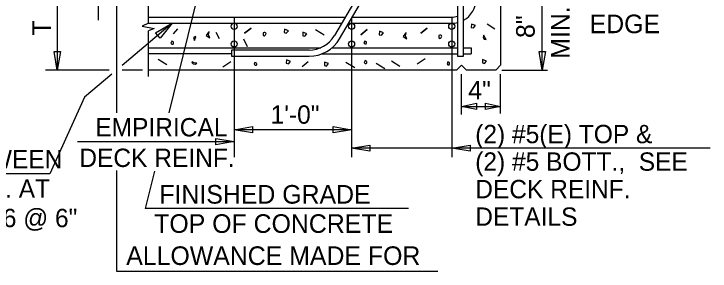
# Model space of a CAD drawing. Extents: x 0 to 34, y 0 to 23.5.
# Drawn here: x 15.91 to 21.84, y 3.54 to 5.73 of the extents above; entities that cross this region are included whole.
import ezdxf

# ---------------------------------------------------------------- set-up
doc = ezdxf.new("R2010")
doc.units = 0
for name, color, linetype in [('BRDG_ANNO_General-Notes', 7, 'Continuous'), ('BRDG_BASE_Dtlctrln', 7, 'Continuous'), ('BRDG_BASE_Obj-Line', 7, 'Continuous'), ('BRDG_BASE_Pattern', 7, 'Continuous'), ('BRDG_BASE_Rebar', 7, 'Continuous'), ('Default', 7, 'Continuous')]:
    doc.layers.add(name, color=color, linetype=linetype)

# ---------------------------------------------------------------- blocks, each defined once
blk = doc.blocks.new('TERM')
at = {"layer": 'Default'}
for p, q in [((-1.6, -0.3), (-1.6, 0.3)), ((-1.6, 0.3), (0, 0)), ((0, 0), (-1.6, -0.3))]:
    blk.add_line(p, q, dxfattribs=at)

msp = doc.modelspace()

# ---------------------------------------------------------------- linework, layer by layer
at = {"layer": 'BRDG_ANNO_General-Notes'}
for p, q in [((16.2812, 5.9219), (16.2812, 5.2552)), ((16.6299, 5.9219), (16.6299, 5.6807)), ((16.7855, 5.9219), (16.7855, 4.8916)), ((17.4854, 5.9219), (17.231, 4.8919)), ((20.4129, 5.2552), (20.4129, 5.9219)), ((17.2603, 5.6546), (16.8331, 5.2948)), ((17.1185, 5.5745), (17.2603, 5.6546)), ((17.2603, 5.6546), (17.1572, 5.5286)), ((17.1572, 5.5286), (17.1185, 5.5745)), ((16.2546, 5.4152), (16.3079, 5.4152)), ((16.2812, 5.2552), (16.2546, 5.4152)), ((16.3079, 5.4152), (16.2812, 5.2552)), ((20.3862, 5.4152), (20.4395, 5.4152)), ((20.4129, 5.2552), (20.3862, 5.4152)), ((20.4395, 5.4152), (20.4129, 5.2552)), ((16.7243, 5.2552), (16.1799, 5.2552)), ((16.7465, 5.2219), (16.5135, 5.0257)), ((17.0066, 5.2552), (16.8351, 5.2552)), ((19.7254, 4.8789), (19.7254, 5.2205)), ((20.0587, 4.8858), (20.0587, 5.2205)), ((20.0691, 5.2552), (20.4584, 5.2552)), ((16.5135, 5.0257), (16.2172, 4.3734)), ((19.7254, 4.9464), (19.8534, 4.973)), ((19.7254, 4.9464), (20.0587, 4.9464)), ((19.8534, 4.9197), (19.7254, 4.9464)), ((19.8534, 4.973), (19.8534, 4.9197)), ((19.9307, 4.9197), (19.9307, 4.973)), ((19.9307, 4.973), (20.0587, 4.9464)), ((20.0587, 4.9464), (19.9307, 4.9197)), ((18.7885, 4.7482), (17.7885, 4.7482)), ((16.4541, 4.6467), (17.7885, 4.6467)), ((19.642, 4.5919), (18.7885, 4.5919)), ((21.8428, 4.5919), (19.642, 4.5919)), ((16.7855, 4.401), (16.7855, 3.5445)), ((17.1086, 4.3961), (17.0298, 4.0772)), ((16.2172, 4.3734), (13.4075, 4.3734)), ((19.2731, 4.0772), (17.0298, 4.0772)), ((16.7855, 3.5445), (19.5245, 3.5445))]:
    msp.add_line(p, q, dxfattribs=at)
at = {"layer": 'BRDG_BASE_Dtlctrln'}
for p, q in [((17.7885, 5.7032), (17.7885, 4.5138)), ((18.7885, 5.7032), (18.7885, 4.5138)), ((19.642, 5.7032), (19.642, 4.5138))]:
    msp.add_line(p, q, dxfattribs=at)
at = {"layer": 'BRDG_BASE_Obj-Line'}
for p, q in [((17.0587, 5.6546), (17.0587, 6.0533)), ((20.0587, 5.8802), (20.0587, 5.2969)), ((17.0587, 5.6546), (17.0043, 5.6296)), ((17.0043, 5.6296), (17.1074, 5.6104)), ((17.1074, 5.6104), (17.0587, 5.5908)), ((17.0587, 5.2021), (17.0587, 5.5908)), ((19.7254, 5.2969), (19.6837, 5.2552)), ((19.7254, 5.2969), (19.767, 5.2552)), ((20.0587, 5.2969), (20.017, 5.2552)), ((19.6837, 5.2552), (17.0587, 5.2552)), ((20.017, 5.2552), (19.767, 5.2552))]:
    msp.add_line(p, q, dxfattribs=at)
at = {"layer": 'BRDG_BASE_Pattern'}
for p, q in [((17.6324, 5.5798), (17.6599, 5.5246)), ((18.482, 5.6024), (18.5564, 5.5556)), ((17.1403, 5.3502), (17.2146, 5.3033)), ((18.7411, 5.3241), (18.8154, 5.2772))]:
    msp.add_line(p, q, dxfattribs=at)
for points in [[(19.81, 5.6483), (19.8086, 5.6186), (19.8266, 5.6144), (19.8439, 5.6345)], [(17.5686, 5.5789), (17.5493, 5.55), (17.5818, 5.5305), (17.5699, 5.5568), (17.5749, 5.5809)], [(17.8778, 5.5697), (17.9331, 5.614)], [(18.0346, 5.5739), (18.0346, 5.5529), (18.0441, 5.5462), (18.047, 5.5489), (18.0551, 5.5572), (18.0607, 5.5683), (18.0567, 5.5739), (18.0511, 5.5766), (18.0484, 5.5766), (18.043, 5.575)], [(18.2162, 5.605), (18.2149, 5.5753), (18.2328, 5.5711), (18.2501, 5.5911)], [(18.3741, 5.5779), (18.3728, 5.5482), (18.3907, 5.5441), (18.408, 5.5641)], [(18.8671, 5.5562), (18.9224, 5.6003)], [(19.026, 5.5862), (19.0246, 5.5566), (19.0426, 5.5524), (19.0598, 5.5724)], [(19.3778, 5.5697), (19.4331, 5.614)], [(17.4432, 5.5322), (17.4517, 5.5073), (17.4517, 5.51), (17.4628, 5.5378), (17.4599, 5.5433)], [(19.2468, 5.5703), (19.2275, 5.5414), (19.2599, 5.5219), (19.2481, 5.5482), (19.2531, 5.5723)], [(19.5321, 5.5513), (19.5321, 5.5304), (19.5416, 5.5236), (19.5445, 5.5263), (19.5526, 5.5346), (19.5581, 5.5457), (19.5541, 5.5513), (19.5486, 5.554), (19.5459, 5.554), (19.5405, 5.5524)], [(19.9118, 5.5494), (19.9087, 5.5339), (19.9191, 5.5186), (19.9364, 5.5153), (19.9226, 5.5335), (19.9166, 5.5525)], [(17.2567, 5.5009), (17.2497, 5.4857), (17.2578, 5.4772), (17.2678, 5.4772), (17.2718, 5.4817), (17.2718, 5.4898), (17.2705, 5.4937), (17.2662, 5.4982)], [(18.9015, 5.5033), (18.8945, 5.4882), (18.9027, 5.4797), (18.9126, 5.4797), (18.9167, 5.4842), (18.9167, 5.4922), (18.9153, 5.4962), (18.911, 5.5007)], [(18.2339, 5.3433), (18.2326, 5.3136), (18.2505, 5.3094), (18.2678, 5.3295)], [(19.9054, 5.3464), (19.9041, 5.3167), (19.922, 5.3125), (19.9393, 5.3326)], [(17.4293, 5.3218), (17.4382, 5.3086), (17.4563, 5.3052), (17.4709, 5.315), (17.4482, 5.3182), (17.4306, 5.3274)], [(17.9655, 5.3203), (17.9586, 5.3052), (17.9667, 5.2967), (17.9766, 5.2967), (17.9807, 5.3011), (17.9807, 5.3092), (17.9793, 5.3132), (17.9751, 5.3177)], [(18.5591, 5.3245), (18.5577, 5.2948), (18.5757, 5.2906), (18.593, 5.3107)], [(18.9033, 5.3366), (18.8964, 5.3215), (18.9045, 5.313), (18.9144, 5.313), (18.9184, 5.3174), (18.9184, 5.3255), (18.9171, 5.3295), (18.9128, 5.334)], [(19.6088, 5.3254), (19.6019, 5.3103), (19.61, 5.3018), (19.6199, 5.3018), (19.624, 5.3062), (19.624, 5.3143), (19.6226, 5.3183), (19.6183, 5.3228)]]:
    msp.add_lwpolyline(points, close=True, dxfattribs=at)
for points in [[(19.9433, 5.6485), (20.0083, 5.6077)], [(17.2704, 5.5637), (17.3081, 5.6073)], [(17.9027, 5.4546), (17.8699, 5.5188)], [(20.0587, 5.4348), (20.0572, 5.4315)], [(20.0572, 5.4315), (20.0587, 5.4299)], [(19.4145, 5.3512), (19.3474, 5.3071)], [(17.7601, 5.3248), (17.693, 5.2807)], [(18.4201, 5.3273), (18.367, 5.2847)], [(18.9985, 5.3144), (19.0716, 5.2685)], [(19.128, 5.3356), (19.2012, 5.2896)]]:
    msp.add_lwpolyline(points, dxfattribs=at)
at = {"layer": 'BRDG_BASE_Rebar'}
for p, q in [((19.3541, 6.7699), (18.6421, 5.5494)), ((18.6871, 5.5232), (19.3991, 6.7438)), ((17.0587, 5.7067), (18.7338, 5.7067)), ((18.7941, 5.7067), (19.642, 5.7067)), ((17.0587, 5.6546), (18.7034, 5.6546)), ((18.7637, 5.6546), (19.642, 5.6546)), ((17.0587, 5.4464), (18.5263, 5.4464)), ((18.4261, 5.4254), (17.766, 5.4254)), ((17.766, 5.4254), (17.766, 5.3733)), ((18.623, 5.4464), (19.6903, 5.4464)), ((19.7421, 5.4464), (19.8087, 5.4464)), ((19.8087, 5.4464), (19.8087, 5.3942)), ((17.766, 5.3943), (17.0587, 5.3943)), ((17.766, 5.3733), (18.4261, 5.3733)), ((18.5365, 5.3943), (19.6901, 5.3943)), ((19.6903, 5.3733), (19.7423, 5.3733)), ((19.7423, 5.3942), (19.8087, 5.3942))]:
    msp.add_line(p, q, dxfattribs=at)
msp.add_lwpolyline([(19.6903, 6.1776), (19.6903, 5.3733), (19.7423, 5.3733), (19.7423, 6.1977)], dxfattribs=at)
for centre in [(17.7885, 5.6286), (18.7885, 5.6286), (19.642, 5.6286), (17.7885, 5.4786), (18.7885, 5.4786), (19.642, 5.4786)]:
    msp.add_circle(centre, 0.026, dxfattribs=at)
for centre, radius, start, end in [((19.642, 5.8623), 0.2083, 298.89739, 0), ((19.642, 5.863), 0.1563, 270, 287.9789), ((19.642, 5.863), 0.2083, 270, 283.3854), ((18.4261, 5.6755), 0.25, 270, 329.73841), ((18.4261, 5.6755), 0.3021, 270, 329.7393)]:
    msp.add_arc(centre, radius, start, end, dxfattribs=at)

# ---------------------------------------------------------------- block references
at = {"layer": 'BRDG_ANNO_General-Notes', "xscale": 0.09765625, "yscale": 0.08680555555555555, "rotation": 180}
for p in [(17.7885, 4.7481), (18.7885, 4.5919), (19.642, 4.5919)]:
    msp.add_blockref('TERM', p, dxfattribs=at)
at = {"layer": 'BRDG_ANNO_General-Notes', "xscale": 0.09765625, "yscale": 0.08680555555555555}
for p in [(18.7885, 4.7481), (17.7885, 4.6467)]:
    msp.add_blockref('TERM', p, dxfattribs=at)

# ---------------------------------------------------------------- texts
at = {"layer": 'BRDG_ANNO_General-Notes'}
for s, height, p in [('MIN.', 0.15833, (20.6467, 5.3521)), ('8"', 0.15833, (20.3489, 5.5289)), ('T', 0.1583, (16.2283, 5.5507))]:
    msp.add_text(s, height=height, rotation=90, dxfattribs=at).set_placement(p)
for s, height, p in [('EDGE', 0.15833, (20.8166, 5.5702)), ('4"', 0.15833, (19.7827, 5.006)), ('1\'-0"', 0.15625, (18.099, 4.7991)), ('EMPIRICAL', 0.15625, (16.6052, 4.6911)), ('(2) #5(E) TOP &', 0.15625, (19.842, 4.6332)), ('#6 @ 12" SPACED BETWEEN', 0.15625, (13.4492, 4.4183)), ('DECK REINF.', 0.15625, (16.4693, 4.4307)), ('(2) #5 BOTT.,  SEE', 0.15625, (19.842, 4.3988)), ('DECK REINF. (#4 @ 12"). AT', 0.15625, (13.4492, 4.1683)), ('FINISHED GRADE', 0.158333, (17.1512, 4.1188)), ('DECK REINF.', 0.15625, (19.842, 4.1644)), ('EXPANSION JOINTS,   #6 @ 6"', 0.15625, (13.4492, 3.9183)), ('DETAILS', 0.15625, (19.842, 3.9301)), ('TOP OF CONCRETE', 0.158333, (17.1074, 3.8698)), ('ALLOWANCE MADE FOR', 0.158333, (16.869, 3.5965))]:
    msp.add_text(s, height=height, dxfattribs=at).set_placement(p)

doc.saveas('drawing.dxf')
